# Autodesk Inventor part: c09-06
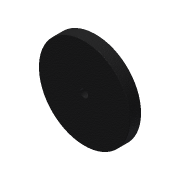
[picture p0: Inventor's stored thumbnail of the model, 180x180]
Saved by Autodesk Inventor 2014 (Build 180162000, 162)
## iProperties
Created: 2010-12
Part Number: c09-06
Document SubType Name: Modeling
Designer: Thom Tremblay
Density: 1 g/cm^3
Material: Generic
Appearance: Iron - Cast
Author: Thom Tremblay
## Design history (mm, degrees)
sketch "Sketch1"
  geometry: C1 r 6.413 at (0, 0); C2 r 74.93 at (0, 0); 1 further point
  constraints: 2 centre point, 2 coincident
  dimensions: "d0" = 12.827 diameter of C1; "d1" = 149.86 diameter of C2
extrude "Extrusion1" new body sketch "Sketch1" distance "d2" = 19.05; taper "d3" = 0 deg
chamfer "Chamfer1" distance "d4" = 0.762; stored, may be unused: second distance "d5" = 3.175, angle "d6" = 45 deg
body "Solid1"
